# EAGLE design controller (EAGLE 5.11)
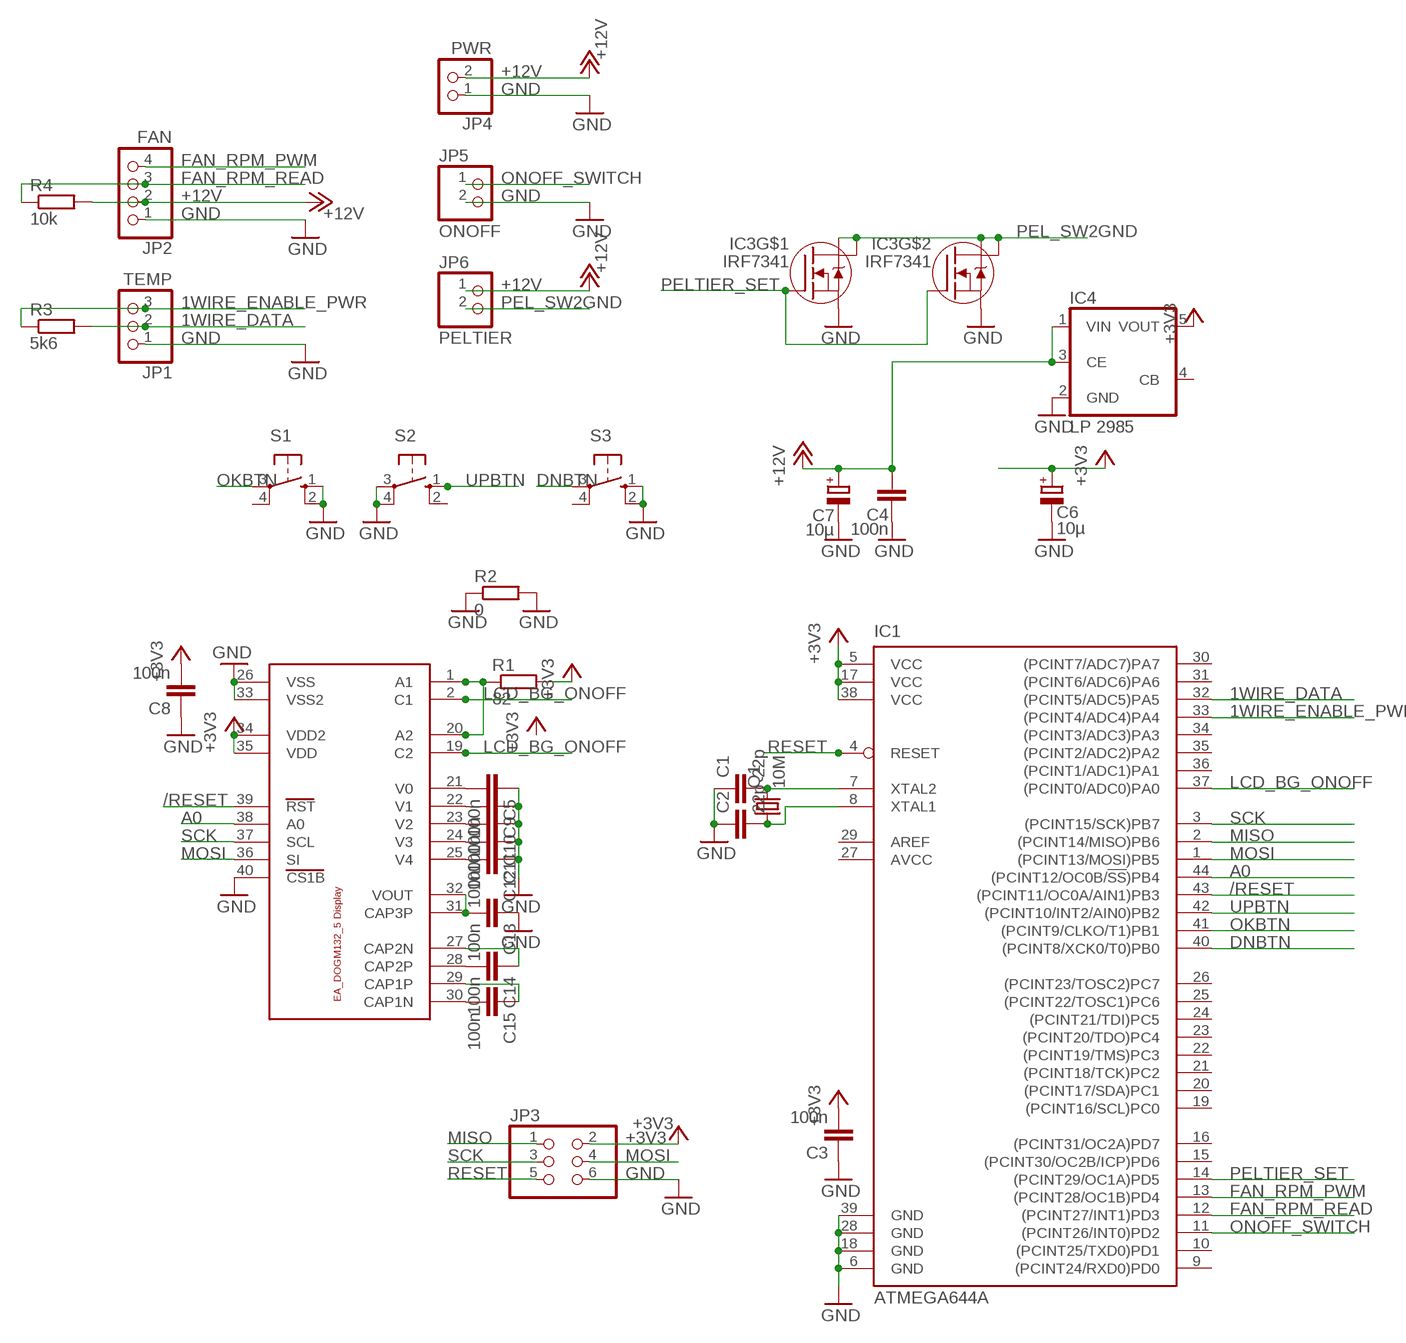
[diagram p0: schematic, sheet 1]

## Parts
C1  22p  C-EUC1206  [C1206]
C2  22p  C-EUC1206  [C1206]
C3  100n  C-EUC1206  [C1206]
C4  100n  C-EUC1206  [C1206]
C5  100n  C-EUC1206  [C1206]
C6  10µ  CPOL-EU153CLV-0505  [153CLV-0505]
C7  10µ  CPOL-EU153CLV-0505  [153CLV-0505]
C8  100n  C-EUC1206  [C1206]
C9  100n  C-EUC1206  [C1206]
C10  100n  C-EUC1206  [C1206]
C11  100n  C-EUC1206  [C1206]
C12  100n  C-EUC1206  [C1206]
C13  100n  C-EUC1206  [C1206]
C14  100n  C-EUC1206  [C1206]
C15  100n  C-EUC1206  [C1206]
IC1  ATMEGA644A  [TQFP44@1]
IC3  IRF7341  IRF7103  [SO8-2]
IC4  LP 2985  TS5205  [SOT25]
JP1  TEMP  PINHD-1X03_2.54-SMD-90°  [1X03SMD/90]
JP2  FAN  PINHD-1X04_2.54-SMD-90°  [1X04SMD/90]
JP3  PINHD-2X3  [2X03]
JP4  PWR  PINHD-1X02_2.54-SMD-90°  [1X02SMD/90]
JP5  ONOFF  PINHD-1X02_2.54-SMD-90°  [1X02SMD/90]
JP6  PELTIER  PINHD-1X02_2.54-SMD-90°  [1X02SMD/90]
Q1  10M  CRYSTALHC49S  [HC49/S]
R1  82  R-EU_R1206  [R1206]
R2  0  R-EU_R1206  [R1206]
R3  5k6  R-EU_R1206  [R1206]
R4  10k  R-EU_R1206  [R1206]
S1  10-XX  [B3F-10XX]
S2  10-XX  [B3F-10XX]
S3  10-XX  [B3F-10XX]
U$1  EA_DOG-M_DISPLAY  [E_DOG-M_DISPLAY]

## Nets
1WIRE_DATA: IC1.32((PCINT5/ADC5)PA5) JP1.2 R3.2
1WIRE_ENABLE_PWR: IC1.33((PCINT4/ADC4)PA4) JP1.3 R3.1
+3V3: C3.2 C6.+ C8.2 IC1.5(VCC) IC1.17(VCC) IC1.38(VCC) IC4.5(VOUT) JP3.2 R1.2 U$1.34(VDD2) U$1.35(VDD)
+12V: C4.2 C7.+ IC4.1(VIN) IC4.3(CE) JP2.2 JP4.2 JP6.1 R4.2
/RESET: IC1.43((PCINT11/OC0A/AIN1)PB3) U$1.39(RST)
A0: IC1.44((PCINT12/OC0B/!SS!)PB4) U$1.38(A0)
DNBTN: IC1.40((PCINT8/XCK0/T0)PB0) S3.3(P)
FAN_RPM_PWM: IC1.13((PCINT28/OC1B)PD4) JP2.4
FAN_RPM_READ: IC1.12((PCINT27/INT1)PD3) JP2.3 R4.1
GND: C1.1 C2.1 C3.1 C4.1 C5.1 C6.- C7.- C8.1 C9.1 C10.1 C11.1 C12.1 C13.1 IC1.6(GND) IC1.18(GND) IC1.28(GND) IC1.39(GND) IC3.1(S) IC3.3(S) IC4.2(GND) JP1.1 JP2.1 JP3.6 JP4.1 JP5.2 R2.1 R2.2 S1.1(S) S1.2(S1) S2.3(P) S2.4(P1) S3.1(S) S3.2(S1) U$1.26(VSS) U$1.33(VSS2) U$1.40(CS1B)
LCD_BG_ONOFF: IC1.37((PCINT0/ADC0)PA0) U$1.2(C1) U$1.19(C2)
MISO: IC1.2((PCINT14/MISO)PB6) JP3.1
MOSI: IC1.1((PCINT13/MOSI)PB5) JP3.4 U$1.36(SI)
N$1: C1.2 IC1.7(XTAL2) Q1.2
N$2: C2.2 IC1.8(XTAL1) Q1.1
N$3: C5.2 U$1.21(V0)
N$4: C9.2 U$1.22(V1)
N$5: C10.2 U$1.23(V2)
N$6: C11.2 U$1.24(V3)
N$7: C12.2 U$1.25(V4)
N$8: C14.2 U$1.28(CAP2P)
N$9: C15.2 U$1.30(CAP1N)
N$10: C13.2 U$1.31(CAP3P) U$1.32(VOUT)
N$11: R1.1 U$1.1(A1) U$1.20(A2)
N$15: C14.1 U$1.27(CAP2N)
N$16: C15.1 U$1.29(CAP1P)
OKBTN: IC1.41((PCINT9/CLKO/T1)PB1) S1.3(P)
ONOFF_SWITCH: IC1.11((PCINT26/INT0)PD2) JP5.1
PEL_SW2GND: IC3.5(D) IC3.6(D) IC3.7(D) IC3.8(D) JP6.2
PELTIER_SET: IC1.14((PCINT29/OC1A)PD5) IC3.2(G) IC3.4(G)
RESET: IC1.4(RESET) JP3.5
SCK: IC1.3((PCINT15/SCK)PB7) JP3.3 U$1.37(SCL)
UPBTN: IC1.42((PCINT10/INT2/AIN0)PB2) S2.1(S)
Unconnected: IC1.9((PCINT24/RXD0)PD0) IC1.10((PCINT25/TXD0)PD1) IC1.15((PCINT30/OC2B/ICP)PD6) IC1.16((PCINT31/OC2A)PD7) IC1.19((PCINT16/SCL)PC0) IC1.20((PCINT17/SDA)PC1) IC1.21((PCINT18/TCK)PC2) IC1.22((PCINT19/TMS)PC3) IC1.23((PCINT20/TDO)PC4) IC1.24((PCINT21/TDI)PC5) IC1.25((PCINT22/TOSC1)PC6) IC1.26((PCINT23/TOSC2)PC7) IC1.29(AREF) IC1.30((PCINT7/ADC7)PA7) IC1.31((PCINT6/ADC6)PA6) IC1.34((PCINT3/ADC3)PA3) IC1.35((PCINT2/ADC2)PA2) IC1.36((PCINT1/ADC1)PA1) IC4.4(CB) S1.4(P1) S2.2(S1) S3.4(P1)

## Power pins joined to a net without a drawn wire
AVCC: IC1.27(AVCC)

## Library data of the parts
C1-C5 C8-C15 = rcl:C-EU: CAPACITOR, European symbol
C6 C7 = rcl:CPOL-EU: POLARIZED CAPACITOR, European symbol
IC1 = atmel:ATMEGA644: 8-bit Microcontroller with 64K Bytes In-System Programmable Flash Source: http://www.atmel.com/dyn/resources/prod_documents/doc2593.pdf
IC3 = irf-2:IRF7103: HEXFET® Power MOSFET Adavanced Process Technology Ultra Low On-Resistance Dual N-Channel MOSFET Surface Mount Available in Tape & Reel Dynamic dv/dt Rating Fast Switching Please connect both Drain-Pins of each FET for thermal Reasons! (Pin 5 with Pin 6, 7 with 8)
IC4 = v-reg:TS5205: 150mA Low Noise LDO Voltage Regulator with Enable TSC [Taiwan Semiconductor Company, Ltd] Source: http://www.taiwansemi.com .. 5205_0409c.pdf
JP1 = pinhead-2:PINHD-1X03: PIN HEADER
JP2 = pinhead-2:PINHD-1X04: PIN HEADER
JP3 = pinhead:PINHD-2X3: PIN HEADER
JP4-JP6 = pinhead-2:PINHD-1X02: PIN HEADER
Q1 = crystal:CRYSTAL: CRYSTAL
R1-R4 = rcl:R-EU_: RESISTOR, European symbol
S1-S3 = switch-omron:10-XX: OMRON SWITCH
U$1 = display_ea_dogm132:EA_DOG-M_DISPLAY

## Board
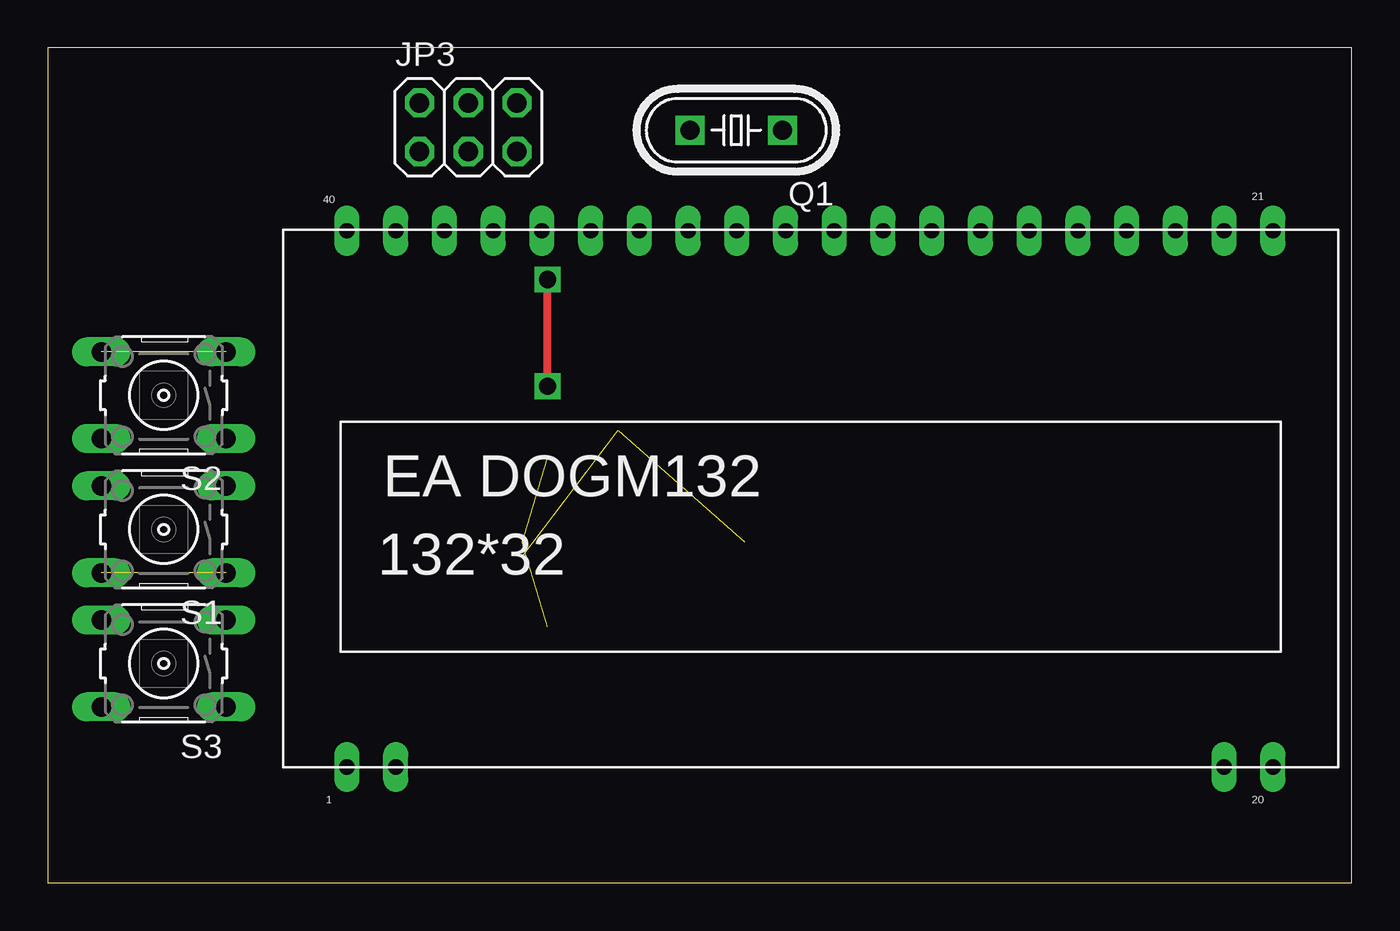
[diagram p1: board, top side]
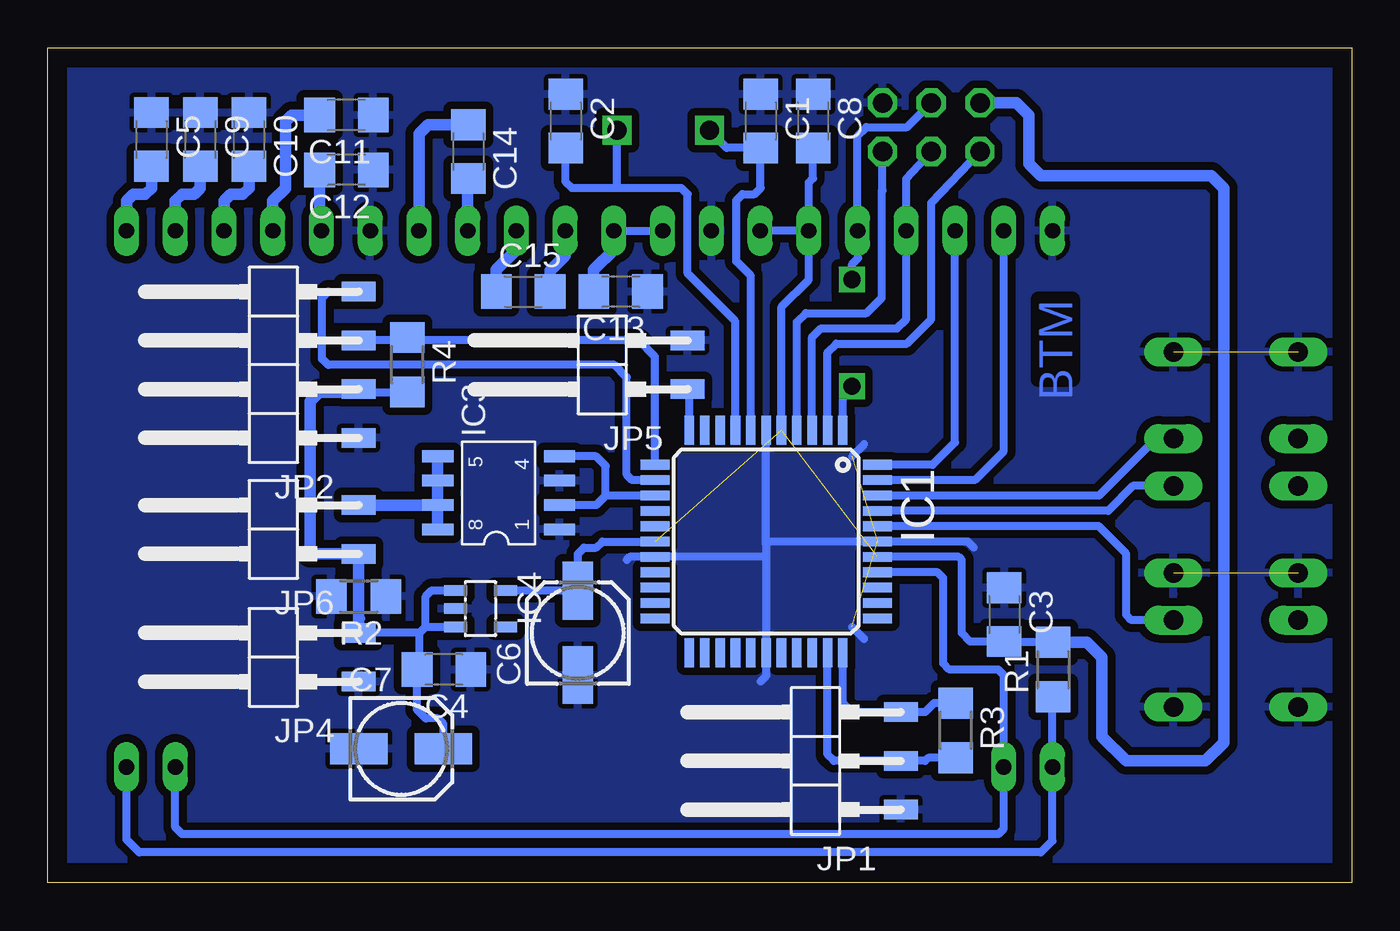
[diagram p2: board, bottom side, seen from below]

Size 67.94 x 43.5 mm. Coordinates in mm from the lower left corner, seen from the top.
Outline: 0,0 67.94,0 67.94,43.5 0,43.5 0,0
Copper layers (1*16): Top 0.035mm / dielectric 1.5mm / Bottom 0.035mm
Design rules "default": minimum track width 10mil, minimum drill 24mil, track to track 8mil, track to pad 8mil, pad to pad 8mil, via to via 8mil, smd to smd 8mil, copper to edge 40mil, drill to drill 8mil, minimum pad ring 10mil, minimum via ring 8mil, stop-mask expansion 4mil, vias tented up to drill 0mil, thermal gap 10mil

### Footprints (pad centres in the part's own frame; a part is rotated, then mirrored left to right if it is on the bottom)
C1206 = smd 1.6 x 1.8: 1 -1.4,0; 2 1.4,0
153CLV-0505 = smd 3 x 1.6: + 2.2,0; - -2.2,0
TQFP44@1 = smd 1.5 x 0.5: 1 -5.8,4; 2 -5.8,3.2; 3 -5.8,2.4; 4 -5.8,1.6; 5 -5.8,0.8; 6 -5.8,0; 7 -5.8,-0.8; 8 -5.8,-1.6; 9 -5.8,-2.4; 10 -5.8,-3.2; 11 -5.8,-4; 23 5.8,-4; 24 5.8,-3.2; 25 5.8,-2.4; 26 5.8,-1.6; 27 5.8,-0.8; 28 5.8,0; 29 5.8,0.8; 30 5.8,1.6; 31 5.8,2.4; 32 5.8,3.2; 33 5.8,4 | smd 0.5 x 1.5: 12 -4,-5.8; 13 -3.2,-5.8; 14 -2.4,-5.8; 15 -1.6,-5.8; 16 -0.8,-5.8; 17 0,-5.8; 18 0.8,-5.8; 19 1.6,-5.8; 20 2.4,-5.8; 21 3.2,-5.8; 22 4,-5.8; 34 4,5.8; 35 3.2,5.8; 36 2.4,5.8; 37 1.6,5.8; 38 0.8,5.8; 39 0,5.8; 40 -0.8,5.8; 41 -1.6,5.8; 42 -2.4,5.8; 43 -3.2,5.8; 44 -4,5.8
SO8-2 = smd 0.61 x 1.626: 1 -2.54,-2.54; 2 -1.27,-2.54; 3 0,-2.54; 4 1.27,-2.54; 5 1.27,3.81; 6 0,3.81; 7 -1.27,3.81; 8 -2.54,3.81
SOT25 = smd 0.55 x 1.2: 1 -0.95,-1.3; 2 0,-1.3; 3 0.95,-1.3; 4 0.95,1.3; 5 -0.95,1.3
1X03SMD/90 = smd 1.016 x 1.778: 1 -1.27,-5.08; 2 1.27,-5.08; 3 3.81,-5.08
1X04SMD/90 = smd 1.016 x 1.778: 1 -1.27,-5.08; 2 1.27,-5.08; 3 3.81,-5.08; 4 6.35,-5.08
2X03 = drill 1.016 octagon: 1 -2.54,-1.27; 2 -2.54,1.27; 3 0,-1.27; 4 0,1.27; 5 2.54,-1.27; 6 2.54,1.27
1X02SMD/90 = smd 1.016 x 1.778: 1 -1.27,-5.08; 2 1.27,-5.08
HC49/S = drill 1 square: 1 -2.413,0; 2 2.413,0
R1206 = smd 1.6 x 1.803: 1 -1.422,0; 2 1.422,0
B3F-10XX = drill 1.016 long: 1 -3.251,2.261; 2 3.251,2.261; 3 -3.251,-2.261; 4 3.251,-2.261
E_DOG-M_DISPLAY = drill 0.8 long: 1 3.334,0; 2 5.874,0; 19 49.054,0; 20 51.594,0; 21 51.594,27.94; 22 49.054,27.94; 23 46.514,27.94; 24 43.974,27.94; 25 41.434,27.94; 26 38.894,27.94; 27 36.354,27.94; 28 33.814,27.94; 29 31.274,27.94; 30 28.734,27.94; 31 26.194,27.94; 32 23.654,27.94; 33 21.114,27.94; 34 18.574,27.94; 35 16.034,27.94; 36 13.494,27.94; 37 10.954,27.94; 38 8.414,27.94; 39 5.874,27.94; 40 3.334,27.94

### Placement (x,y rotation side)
C1  30.8,39.69 270 bottom
C2  40.96,39.69 270 bottom
C3  18.1,13.97 270 bottom
C4  47.31,11.11 180 bottom
C5  62.55,38.73 270 bottom
C6  40.32,13.02 90 bottom
C7  49.53,6.99 0 bottom
C8  28.07,39.69 270 bottom
C9  60.01,38.73 270 bottom
C10  57.47,38.73 270 bottom
C11  52.39,40.01 180 bottom
C12  52.39,37.15 180 bottom
C13  38.1,30.8 180 bottom
C14  46.04,38.1 270 bottom
C15  43.18,30.8 0 bottom
IC1  30.51,17.78 270 bottom
IC3  43.81,20.95 90 bottom
IC4  45.4,14.29 270 bottom
JP1  28.57,5.08 90 bottom
JP2  56.83,24.45 90 bottom
JP3  21.91,39.37 0 top
JP4  56.83,11.75 90 bottom
JP5  39.69,26.99 90 bottom
JP6  56.83,18.41 90 bottom
Q1  35.88,39.21 180 top
R1  15.56,11.11 90 bottom
R2  51.75,14.92 180 bottom
R3  20.64,7.94 270 bottom
R4  49.21,26.99 270 bottom
S1  6.03,18.41 180 top
S2  6.03,25.4 180 top
S3  6.03,11.43 180 top
U$1  12.26,6.03 0 top

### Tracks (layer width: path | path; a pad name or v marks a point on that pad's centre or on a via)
1WIRE_DATA
  Bottom 0.406: R3.2 22.06,6.52 22.23,6.35 JP1.2 26.99,6.35 27.31,6.67 IC1.32
1WIRE_ENABLE_PWR
  Bottom 0.406: R3.1 21.76,9.36 22.23,8.89 JP1.3 26.04,8.89 26.51,9.37 IC1.33
+3V3  (2 unrouted)
  Bottom 0.406: IC1.5 29.71,30.01 28.29,31.43 U$1.35 | U$1.35 U$1.34 | U$1.35 28.29,36.48 28.07,36.7 C8.2 | IC1.38 20.47,16.98 20.32,16.83 20.32,13.02 19.87,12.57 C3.2 18.06,12.53 R1.2 | IC4.5 44.08,15.22 C6.+ 40.32,17.14 40.01,17.46 39.37,17.46 39.05,17.78 IC1.17
  Bottom 0.61: JP3.2 17.46,40.64 16.83,40.01 16.83,37.47 16.19,36.83 7.3,36.83 6.67,36.2 6.67,7.3 7.62,6.35 11.75,6.35 13.02,7.62 13.02,11.75 13.8,12.53 R1.2
+12V
  Bottom 0.406: R4.2 51.6,25.57 JP2.2 | 51.62,13.78 JP4.2 48.58,13.02 | 48.26,13.34 IC4.3 | 48.58,13.02 48.26,13.34 | IC4.1 47.95,15.24 48.26,14.92 48.26,13.34 | 48.58,13.02 48.58,11.24 C4.2 48.71,9.02 48.26,8.57 47.62,8.57 47.33,8.28 C7.+
  Bottom 0.61: 51.6,25.57 53.81,25.57 54.29,25.08 54.29,17.14 JP6.1 JP4.2
/RESET
  Bottom 0.406: IC1.43 19.64,20.98 18.13,22.49 U$1.39
A0
  Bottom 0.406: U$1.38 20.67,22.95 21.84,21.78 IC1.44
DNBTN
  Bottom 0.406: IC1.40 13.18,18.58 11.75,17.14 11.75,13.97 11.47,13.69 S3.3
FAN_RPM_PWM
  Bottom 0.406: IC1.13 37.49,20.98 37.78,21.27 37.78,26.35 38.42,26.99 53.34,26.99 53.66,27.3 53.66,30.48 53.34,30.8 JP2.4
FAN_RPM_READ
  Bottom 0.406: IC1.12 36.31,27.42 37.15,28.26 49.21,28.26 | 49.21,28.26 JP2.3 | 49.21,28.26 R4.1
GND  (4 unrouted)
  Bottom 0.406: 30.51,16.98 IC1.18 37.63,16.98 37.78,16.83 | 30.51,17.62 30.51,16.98 | 30.51,17.62 IC1.6 | 30.51,17.62 30.35,17.78 IC1.39 20,17.78 19.68,17.46 | 30.51,16.98 IC1.28 30.51,10.76 30.8,10.48 | 26.04,22.23 25.4,22.86 | 26.04,13.34 25.4,12.7
  pour Bottom: 26.46,21.75 26.46,13.81 34.4,13.81 34.4,21.75
  pour Bottom (isolate 0.406): -0.05,0 68.42,0 68.42,43.72 -0.05,43.72
LCD_BG_ONOFF
  Bottom 0.406: IC1.37 21.58,16.18 21.27,15.88 21.27,11.43 20.95,11.11 18.41,11.11 18.13,10.83 U$1.2 18.13,2.83 18.41,2.54 60.96,2.54 61.31,2.89 U$1.19
MISO
  Bottom 0.406: IC1.2 27.31,27.65 26.86,28.1 23.18,28.1 21.91,29.37 21.91,35.43 JP3.1
MOSI  (via drill 0.9)
  Top 0.406: v26.04,25.88 v26.04,31.43
  Bottom 0.406: IC1.1 26.51,25.4 v26.04,25.88 | v26.04,31.43 26.04,32.23 25.72,32.54 25.72,33.94 U$1.36 25.75,38.92 25.29,39.38 23.17,39.38 JP3.4
N$1
  Bottom 0.406: IC1.7 31.31,31.63 32.07,32.38 32.07,35.56 31.75,35.88 31.11,35.88 30.8,36.2 C1.2 32.57,38.29 33.47,39.18 Q1.2
N$2
  Bottom 0.406: IC1.8 32.11,29.25 34.61,31.75 34.61,35.88 34.92,36.2 38.42,36.2 | 38.42,36.2 40.64,36.2 40.96,36.51 C2.2 | Q1.1 38.29,36.32 38.42,36.2
N$3
  Bottom 0.61: C5.2 62.55,36.2 62.87,35.88 63.5,35.88 63.85,35.53 U$1.21
N$4
  Bottom 0.61: C9.2 60.01,36.2 60.33,35.88 60.96,35.88 61.31,35.53 U$1.22
N$5
  Bottom 0.61: C10.2 57.47,36.2 57.78,35.88 58.42,35.88 58.77,35.53 U$1.23
N$6
  Bottom 0.61: C11.2 55.24,40.01 55.56,39.69 55.56,36.2 56.23,35.53 U$1.24
N$7
  Bottom 0.61: C12.2 53.79,34.07 U$1.25
N$8
  Bottom 0.61: C14.2 46.07,36.7 U$1.28
N$9
  Bottom 0.61: U$1.30 40.99,32.67 41.78,31.88 C15.2
N$10
  Bottom 0.406: U$1.31 U$1.32
  Bottom 0.61: U$1.31 38.45,32.99 39.5,31.94 C13.2
N$11
  Bottom 0.406: R1.1 15.59,9.66 U$1.1 15.59,2.19 16.19,1.59 63.18,1.59 63.85,2.25 U$1.20
N$15
  Bottom 0.61: C14.1 48.13,39.5 48.61,39.02 U$1.27
N$16
  Bottom 0.61: U$1.29 43.53,32.99 44.58,31.94 C15.1
OKBTN
  Bottom 0.406: S1.3 11.39,20.68 12.69,19.38 IC1.41
ONOFF_SWITCH
  Bottom 0.406: IC1.11 34.51,25.62 JP5.1
PEL_SW2GND
  Bottom 0.61: IC3.5 IC3.6 IC3.7 | IC3.7 IC3.8 | IC3.7 JP6.2
PELTIER_SET
  Bottom 0.406: IC1.14 38.88,20.18 | 38.88,20.18 39.37,19.68 IC3.2 | IC3.4 39.37,22.23 38.88,21.73 38.88,20.18
RESET
  Bottom 0.406: IC1.4 28.91,29.22 28.45,29.69 25.27,29.69 24.48,30.48 24.48,36.04 24.45,36.07 JP3.5
SCK
  Bottom 0.406: IC1.3 28.11,28.43 27.65,28.89 23.68,28.89 23.21,29.37 U$1.37 23.21,36.67 JP3.3
UPBTN
  Bottom 0.406: S2.1 10.2,23.14 13.16,20.18 IC1.42

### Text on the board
Bottom: BTM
